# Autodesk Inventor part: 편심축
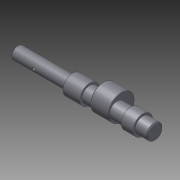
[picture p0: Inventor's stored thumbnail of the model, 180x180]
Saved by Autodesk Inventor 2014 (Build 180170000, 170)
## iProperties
Company: 한국ATC센터
Created: 2015-12
Part Number: 편심축
Document SubType Name: Modeling
Designer: mdu
Density: 7.86 g/cm^3
Mass: 222.98 g
Surface Area: 83.5896 cm^2
Volume: 28.369 cm^3
Material: 강철, 연강
Appearance: 강철
Author: mdu
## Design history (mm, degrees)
sketch "스케치1"
  geometry: L1 (-86, 0)-(86, 0); L2 (-86, 0)-(-86, 6); L3 (-86, 6)-(-32, 6); L4 (-32, 6)-(-32, 9.5); L5 (-32, 9.5)-(-15.5, 9.5); L6 (-15.5, 9.5)-(-15.5, 7.5); L7 (-15.5, 7.5)-(48, 7.5); L8 (86, 6)-(86, 0); L9 (36, 7.5)-(36, 9.5); L10 (36, 9.5)-(24.5, 9.5); L11 (24.5, 9.5)-(24.5, 7.5); L12 (48, 7.5)-(48, 6); L13 (48, 6)-(86, 6); 2 further points
  constraints: 26 end point, 6 parallel, 6 perpendicular, 2 point on line, 1 coincident, 1 horizontal, 1 midpoint
  dimensions: "d1" = 12 diameter of L3 L1; "d2" = 15 diameter of L7 L1; "d4" = 16.5 distance of L4.end L5.end; "d5" = 19 diameter of L5 L1; "d24" = 11.5 distance of L9.end L10.end; "d25" = 19 diameter of L10 L1; "d27" = 40 distance between parallel lines of L11 L6; "d28" = 54 distance of L2.end L3.end; "d29" = 50 distance between parallel lines of L8 L9; "d41" = 38 distance between parallel lines of L8 L12; "d42" = 12 diameter of L13 L1
revolve "회전1" stored, may be unused: angle "d6" = 90 deg
node "작업 평면1"
sketch "스케치2"
  geometry: C1 r 7.5 at (0, 0) reference; C2 r 12.5 at (0, 4.5); 1 further point
  constraints: 1 centre point, 1 vertical alignment
  dimensions: "d8" = 4.5 distance of point (0, 0) C2.centre; "d9" = 25 diameter of C2
extrude "돌출1" join sketch "스케치2" distance "d10" = 18; taper "d11" = 0 deg
chamfer "모따기1" distance "d12" = 1; stored, may be unused: second distance "d13" = 2, angle "d14" = 45 deg
chamfer "모따기2" distance "d15" = 0.5; stored, may be unused: second distance "d16" = 2, angle "d17" = 45 deg
node "작업 평면2"
sketch "스케치3"
  geometry: L1 (4, -2)-(18, -2); L2 (18, 2)-(4, 2); L3 (27, 5)-(27, -5) reference; A1 r 2 centre (18, 0) between (18, -2) and (18, 2); A2 r 2 centre (4, 0) between (4, 2) and (4, -2); 2 further points
  constraints: 4 end point, 4 point on circle, 4 tangent, 2 centre point, 1 horizontal, 1 horizontal alignment, 1 midpoint, 1 parallel
  dimensions: "d18" = 7 distance edge to line of A1 L3; "d19" = 4 distance between parallel lines of L2 L1; "d20" = 18 dimension on A1 A2
extrude "돌출2" cut sketch "스케치3" distance "d21" = 2.5; taper "d22" = 0 deg
revolve "회전2" stored, may be unused: angle "d26" = 90 deg
node "작업 평면3"
sketch "스케치4"
  geometry: L1 (44, 5)-(44, -5) reference; 2 further points
  constraints: 1 horizontal alignment
  dimensions: "d30" = 12 distance from line of point (32, 0) L1
hole "구멍1" sketch "스케치4" at (32, 0) diameter "d31" = 6; stored, may be unused: countersink angle "d35" = 90 deg, drill point angle "d37" = 118 deg; dims "d32" = 6, "d33" = 14, "d34" = 3, "d36" = 8
node "작업 평면4"
sketch "스케치5"
  geometry: C1 r 3 at (32, 0) reference; C2 r 8 at (32, 0); 2 further points
  constraints: 1 centre point, 1 coincident, 1 other
  dimensions: "d38" = 16 diameter of C2
extrude "돌출3" cut sketch "스케치5" distance "d39" = 3; taper "d40" = 0 deg
sketch "스케치6"
  geometry: L1 (-85, -6)-(-32, -6) reference; L2 (-86, -5)-(-86, 5) reference; L3 (-85, 6)-(-32, 6) reference; L4 (-64, 6)-(-64, -6); L5 (-64, -6)-(-62.5, -6); L6 (-64, -4.5)-(-62.5, -6); L7 (-64, -6)-(-64, -4.5); 2 further points
  constraints: 8 end point, 4 point on line, 2 perpendicular, 1 coincident
  dimensions: "d43" = 22 distance between parallel lines of L4 L2; "d44" = 45 deg angle of L6 L7; "d45" = 3 diameter of L5.end L4
revolve "회전3" stored, may be unused: angle "d46" = 90 deg
node "작업점1"
chamfer "모따기3" distance "d47" = 0.5; stored, may be unused: second distance "d48" = 2, angle "d49" = 45 deg
sketch "스케치7"
  geometry: C1 r 7.5 at (0, 0) reference; 1 further point
extrude "돌출4" cut sketch "스케치7" stored distance "d50" = 10; taper "d51" = 0 deg
chamfer "모따기4" distance "d52" = 1; stored, may be unused: second distance "d53" = 2, angle "d54" = 45 deg
node "작업 평면5"
hole "구멍2" diameter "d63" = 4.917; stored, may be unused: countersink angle "d67" = 90 deg, drill point angle "d69" = 118 deg; dims "d64" = 12, "d65" = 4, "d66" = 2, "d68" = 15, "d72" = 10, "d73" = 10
node "솔리드1"
node "투영된 루프1"
other parameters: "d7" = 8.5
